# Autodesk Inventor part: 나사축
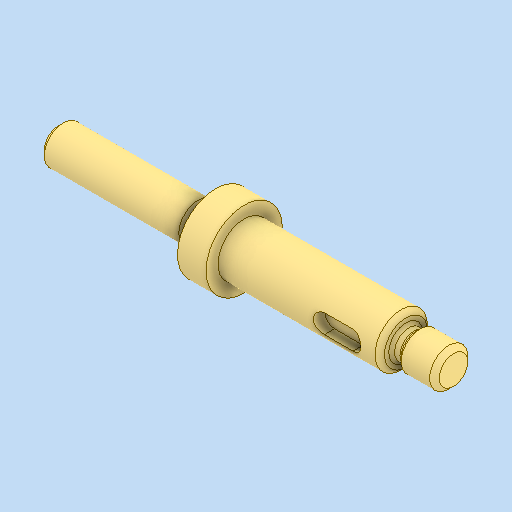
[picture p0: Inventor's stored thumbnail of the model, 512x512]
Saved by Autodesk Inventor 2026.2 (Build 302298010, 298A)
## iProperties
Created: 2026-08
Part Number: 나사축
Material: 강철, 탄소
Document SubType Name: Modeling
Designer: PC2-02
Density: 7.85 g/cm^3
Appearance: 기본값
Author: jhkim
Sending System: Autodesk Inventor 2027
Preprocessor: ST-DEVELOPER v20.1
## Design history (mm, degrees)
feature "솔리드1"
node "솔리드2"
